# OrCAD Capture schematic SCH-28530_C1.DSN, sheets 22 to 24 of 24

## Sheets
22 24 PoE: size C
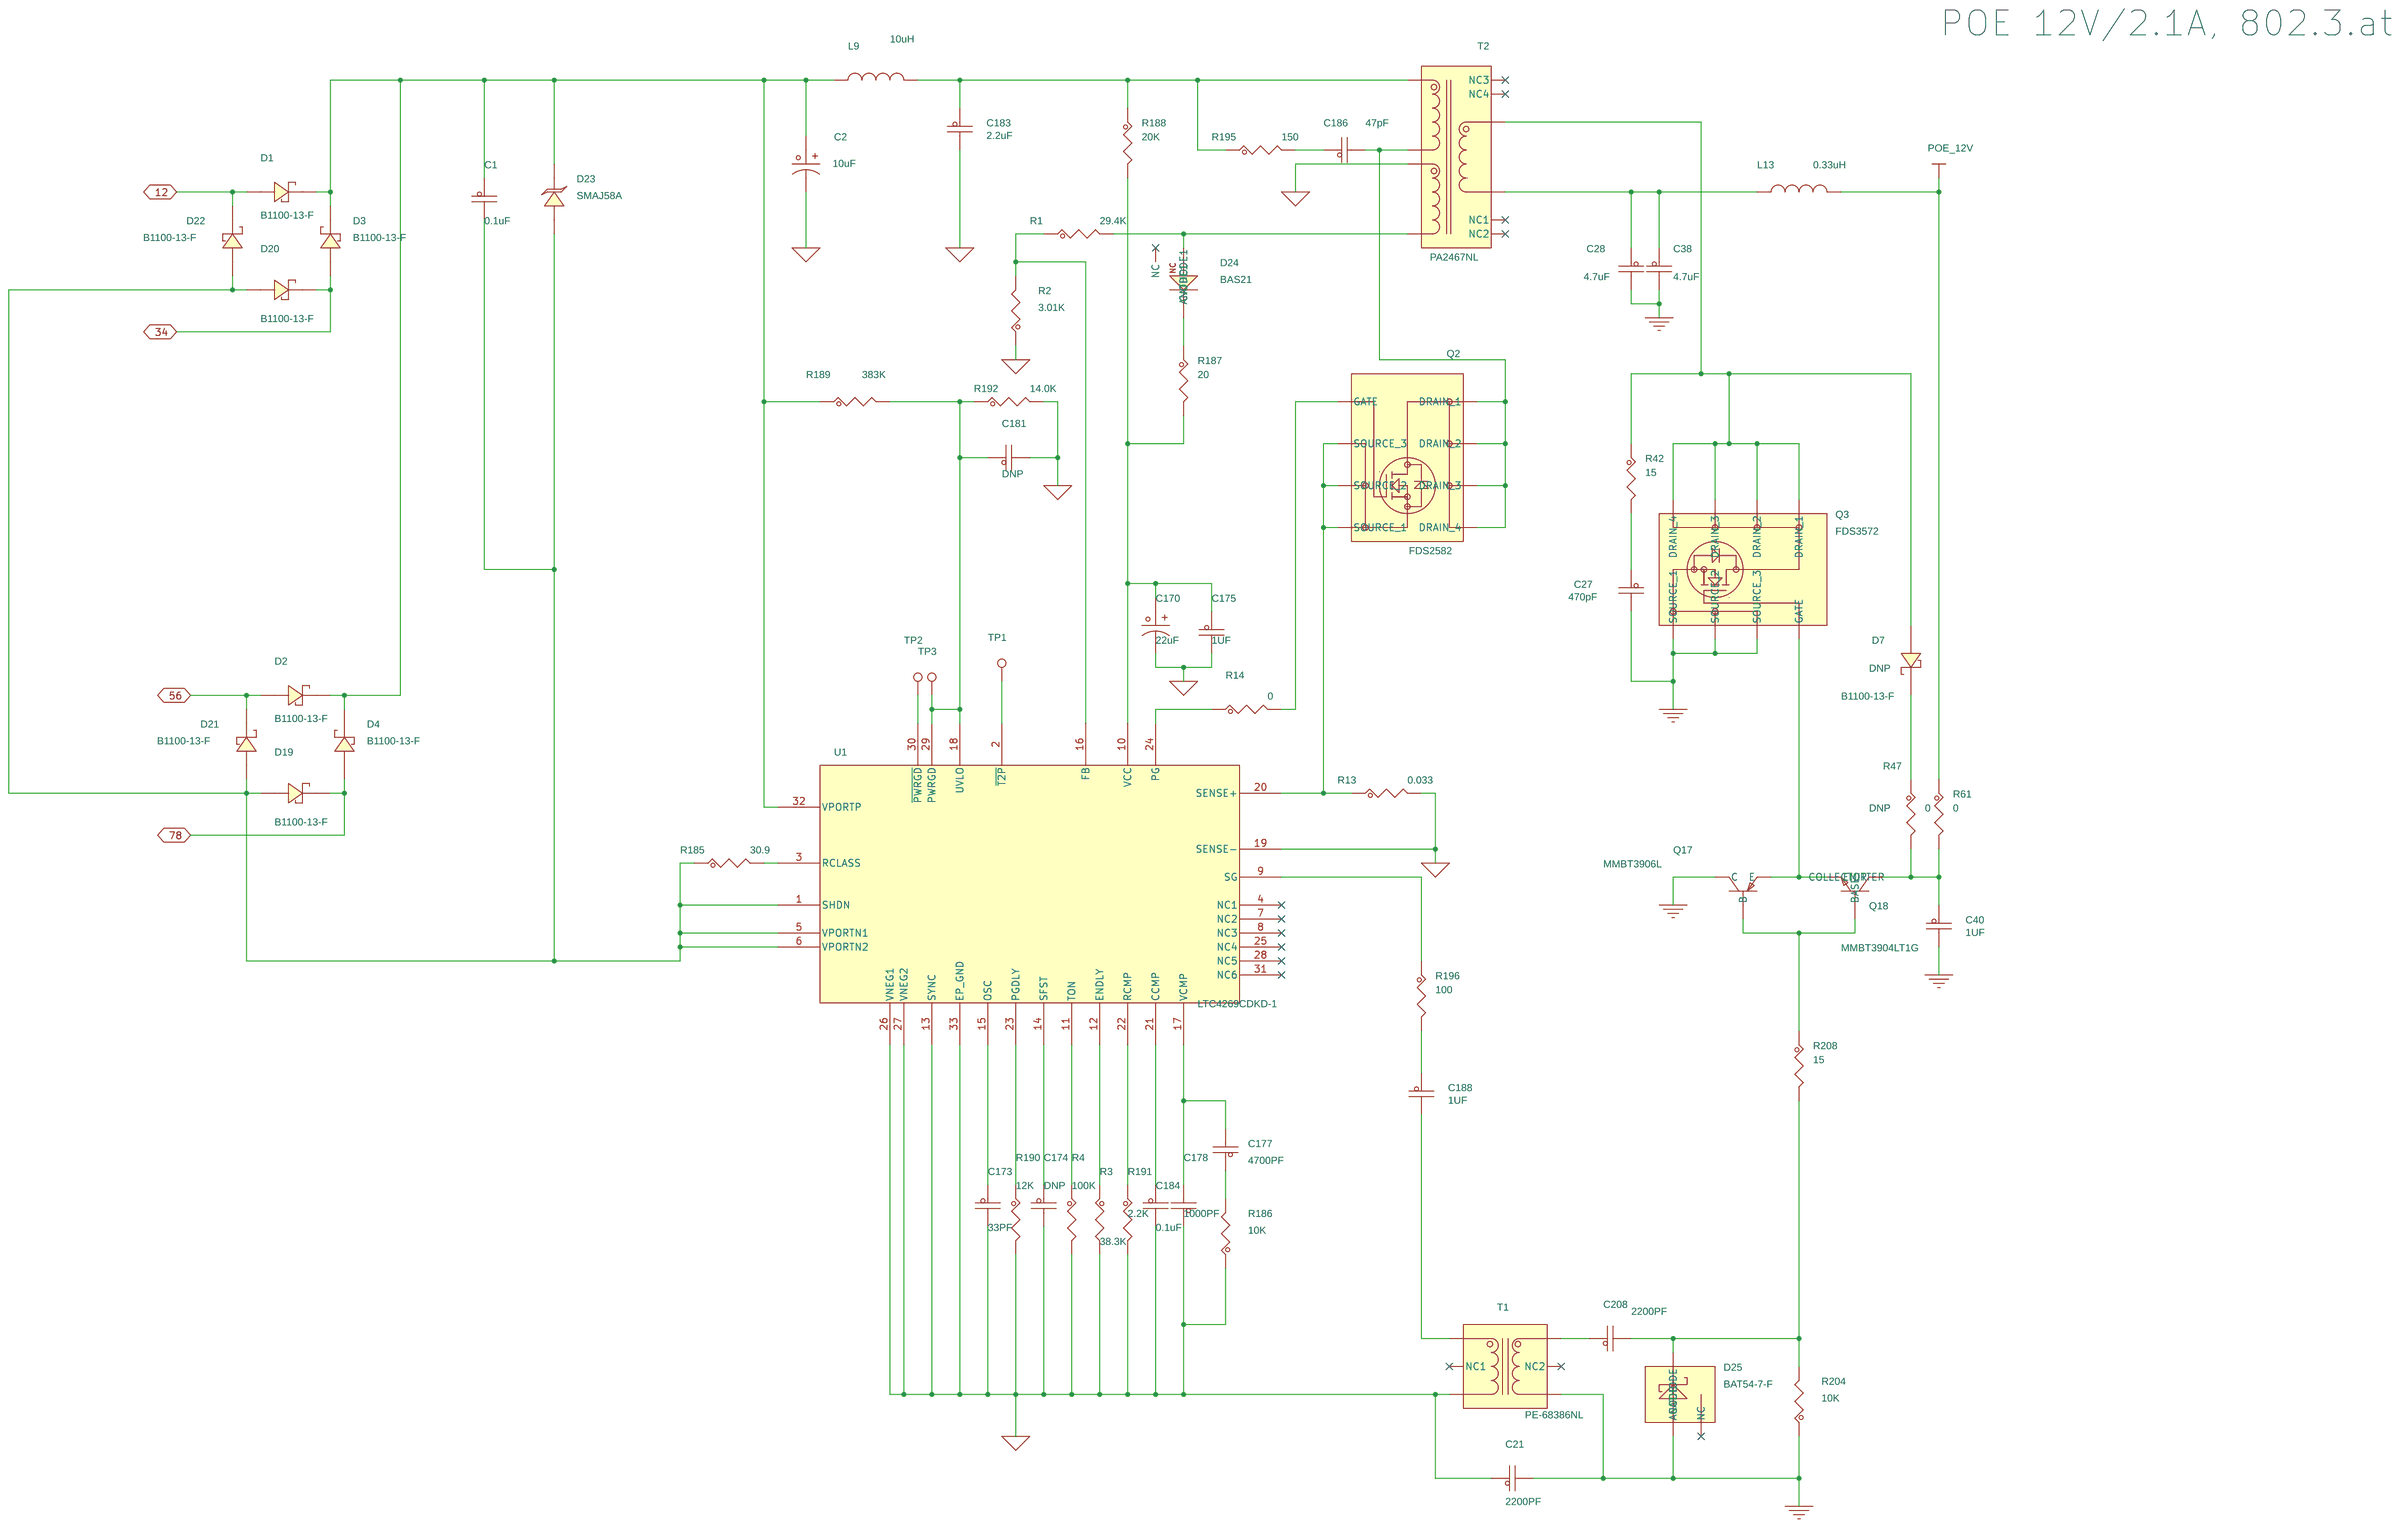
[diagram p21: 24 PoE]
23 21 V85/2V1/1V2/5V0: size C
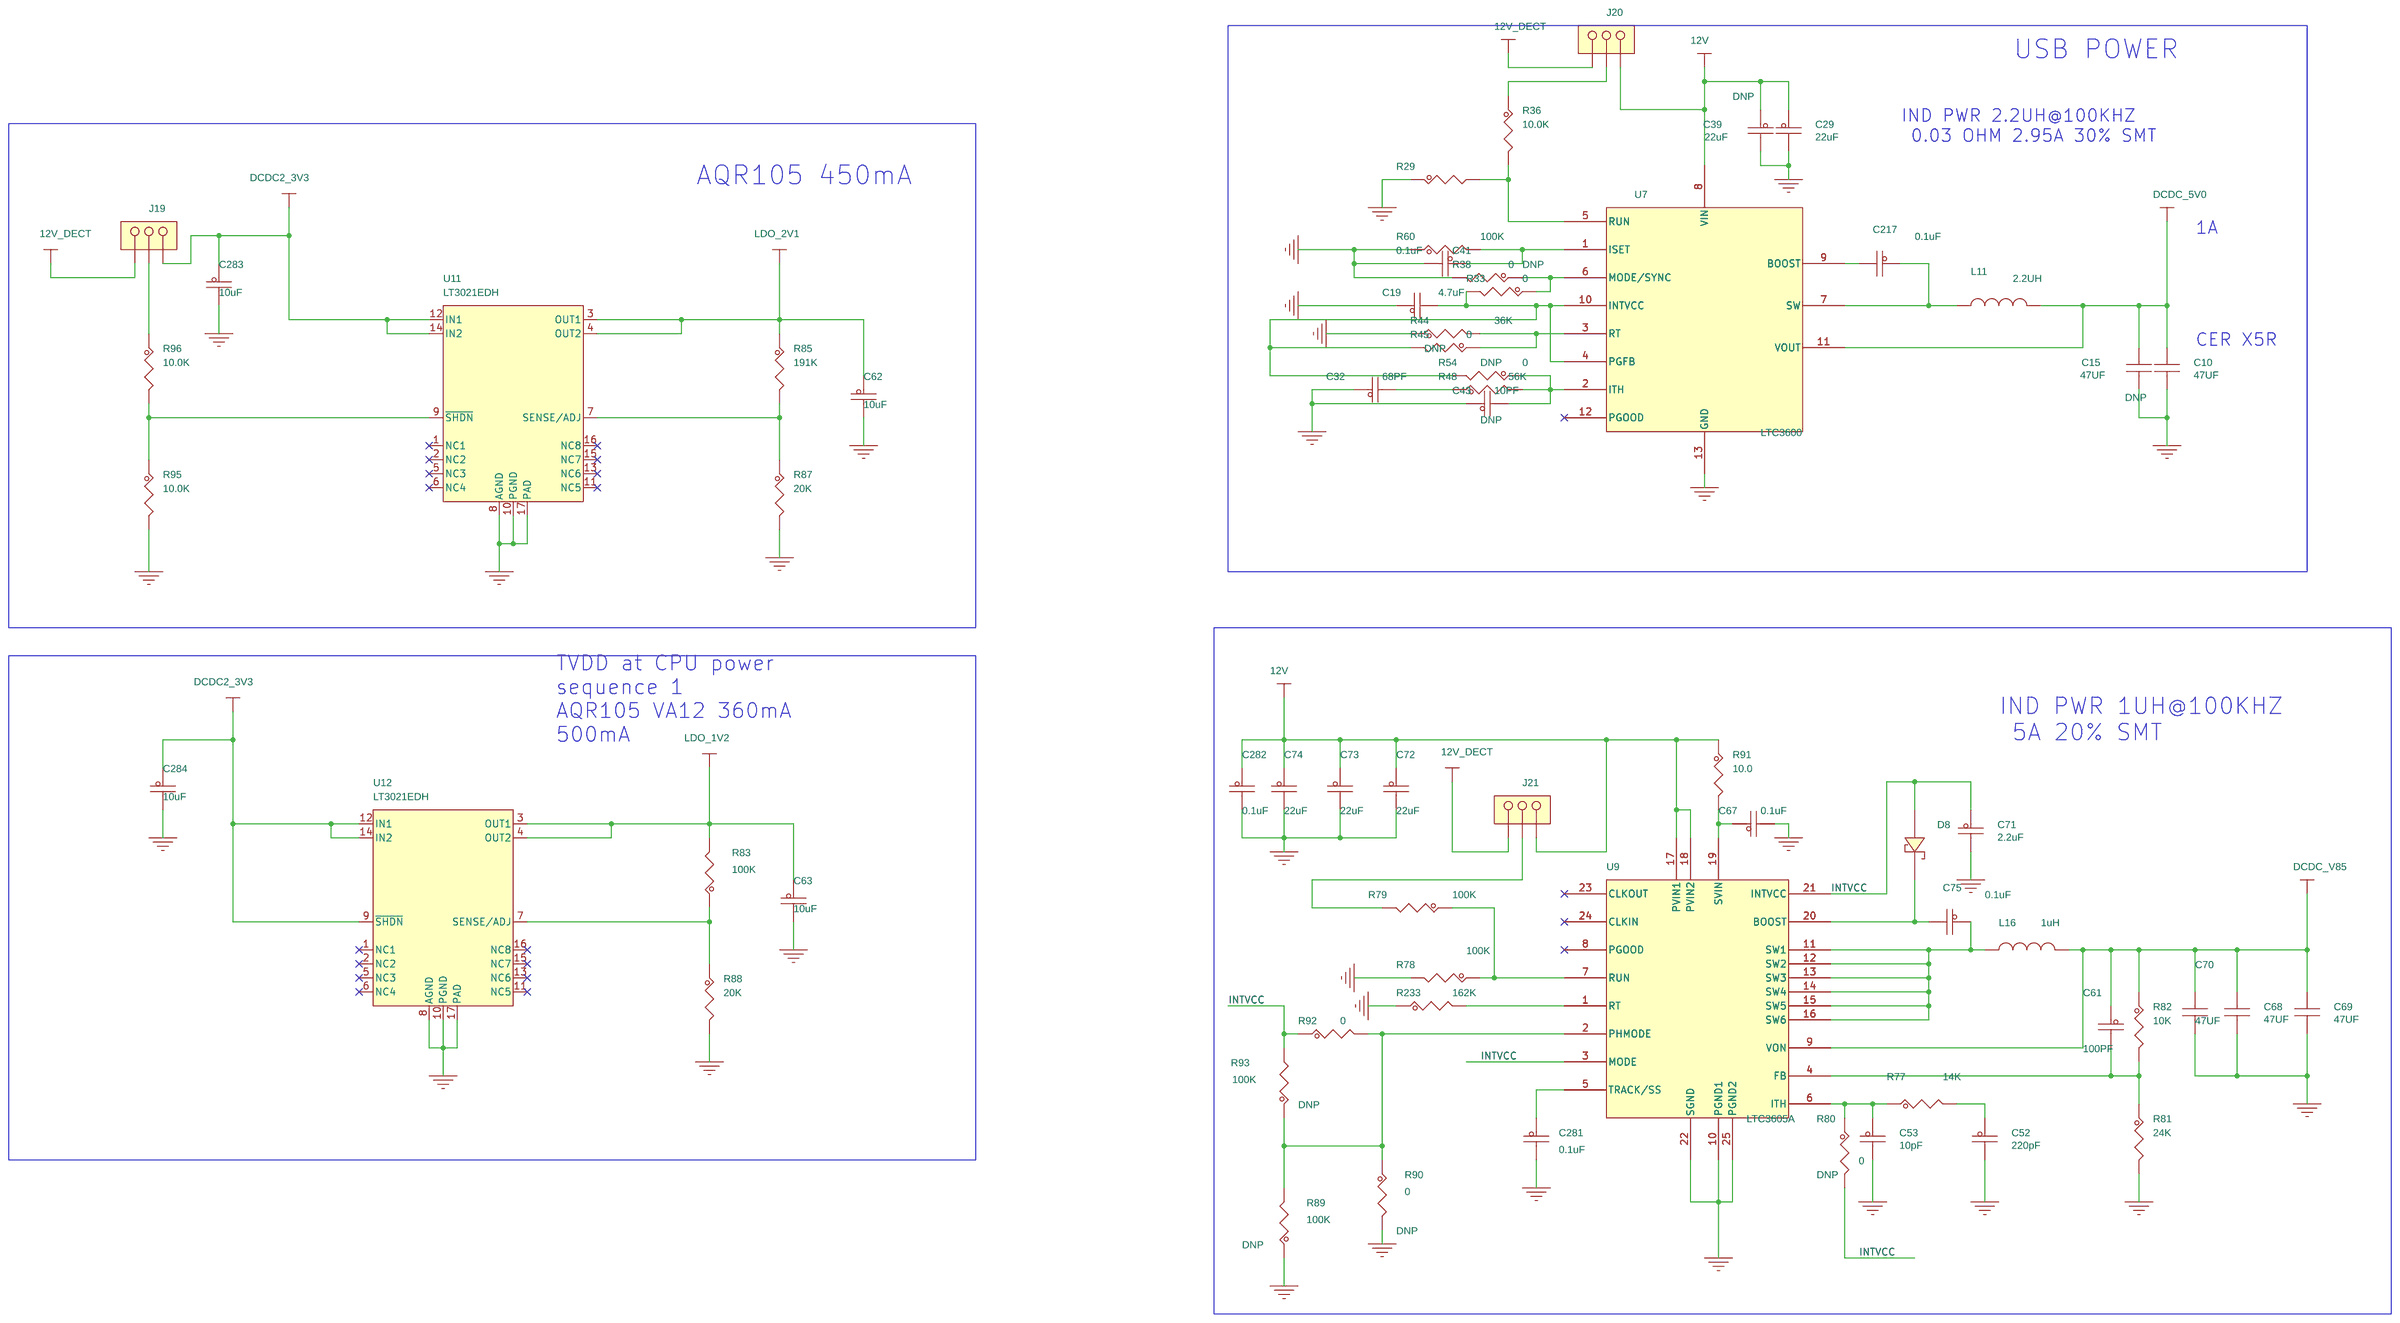
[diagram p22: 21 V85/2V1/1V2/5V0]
24 20 VR500(1V5/1V8/1V2/1V35/2V5): size C
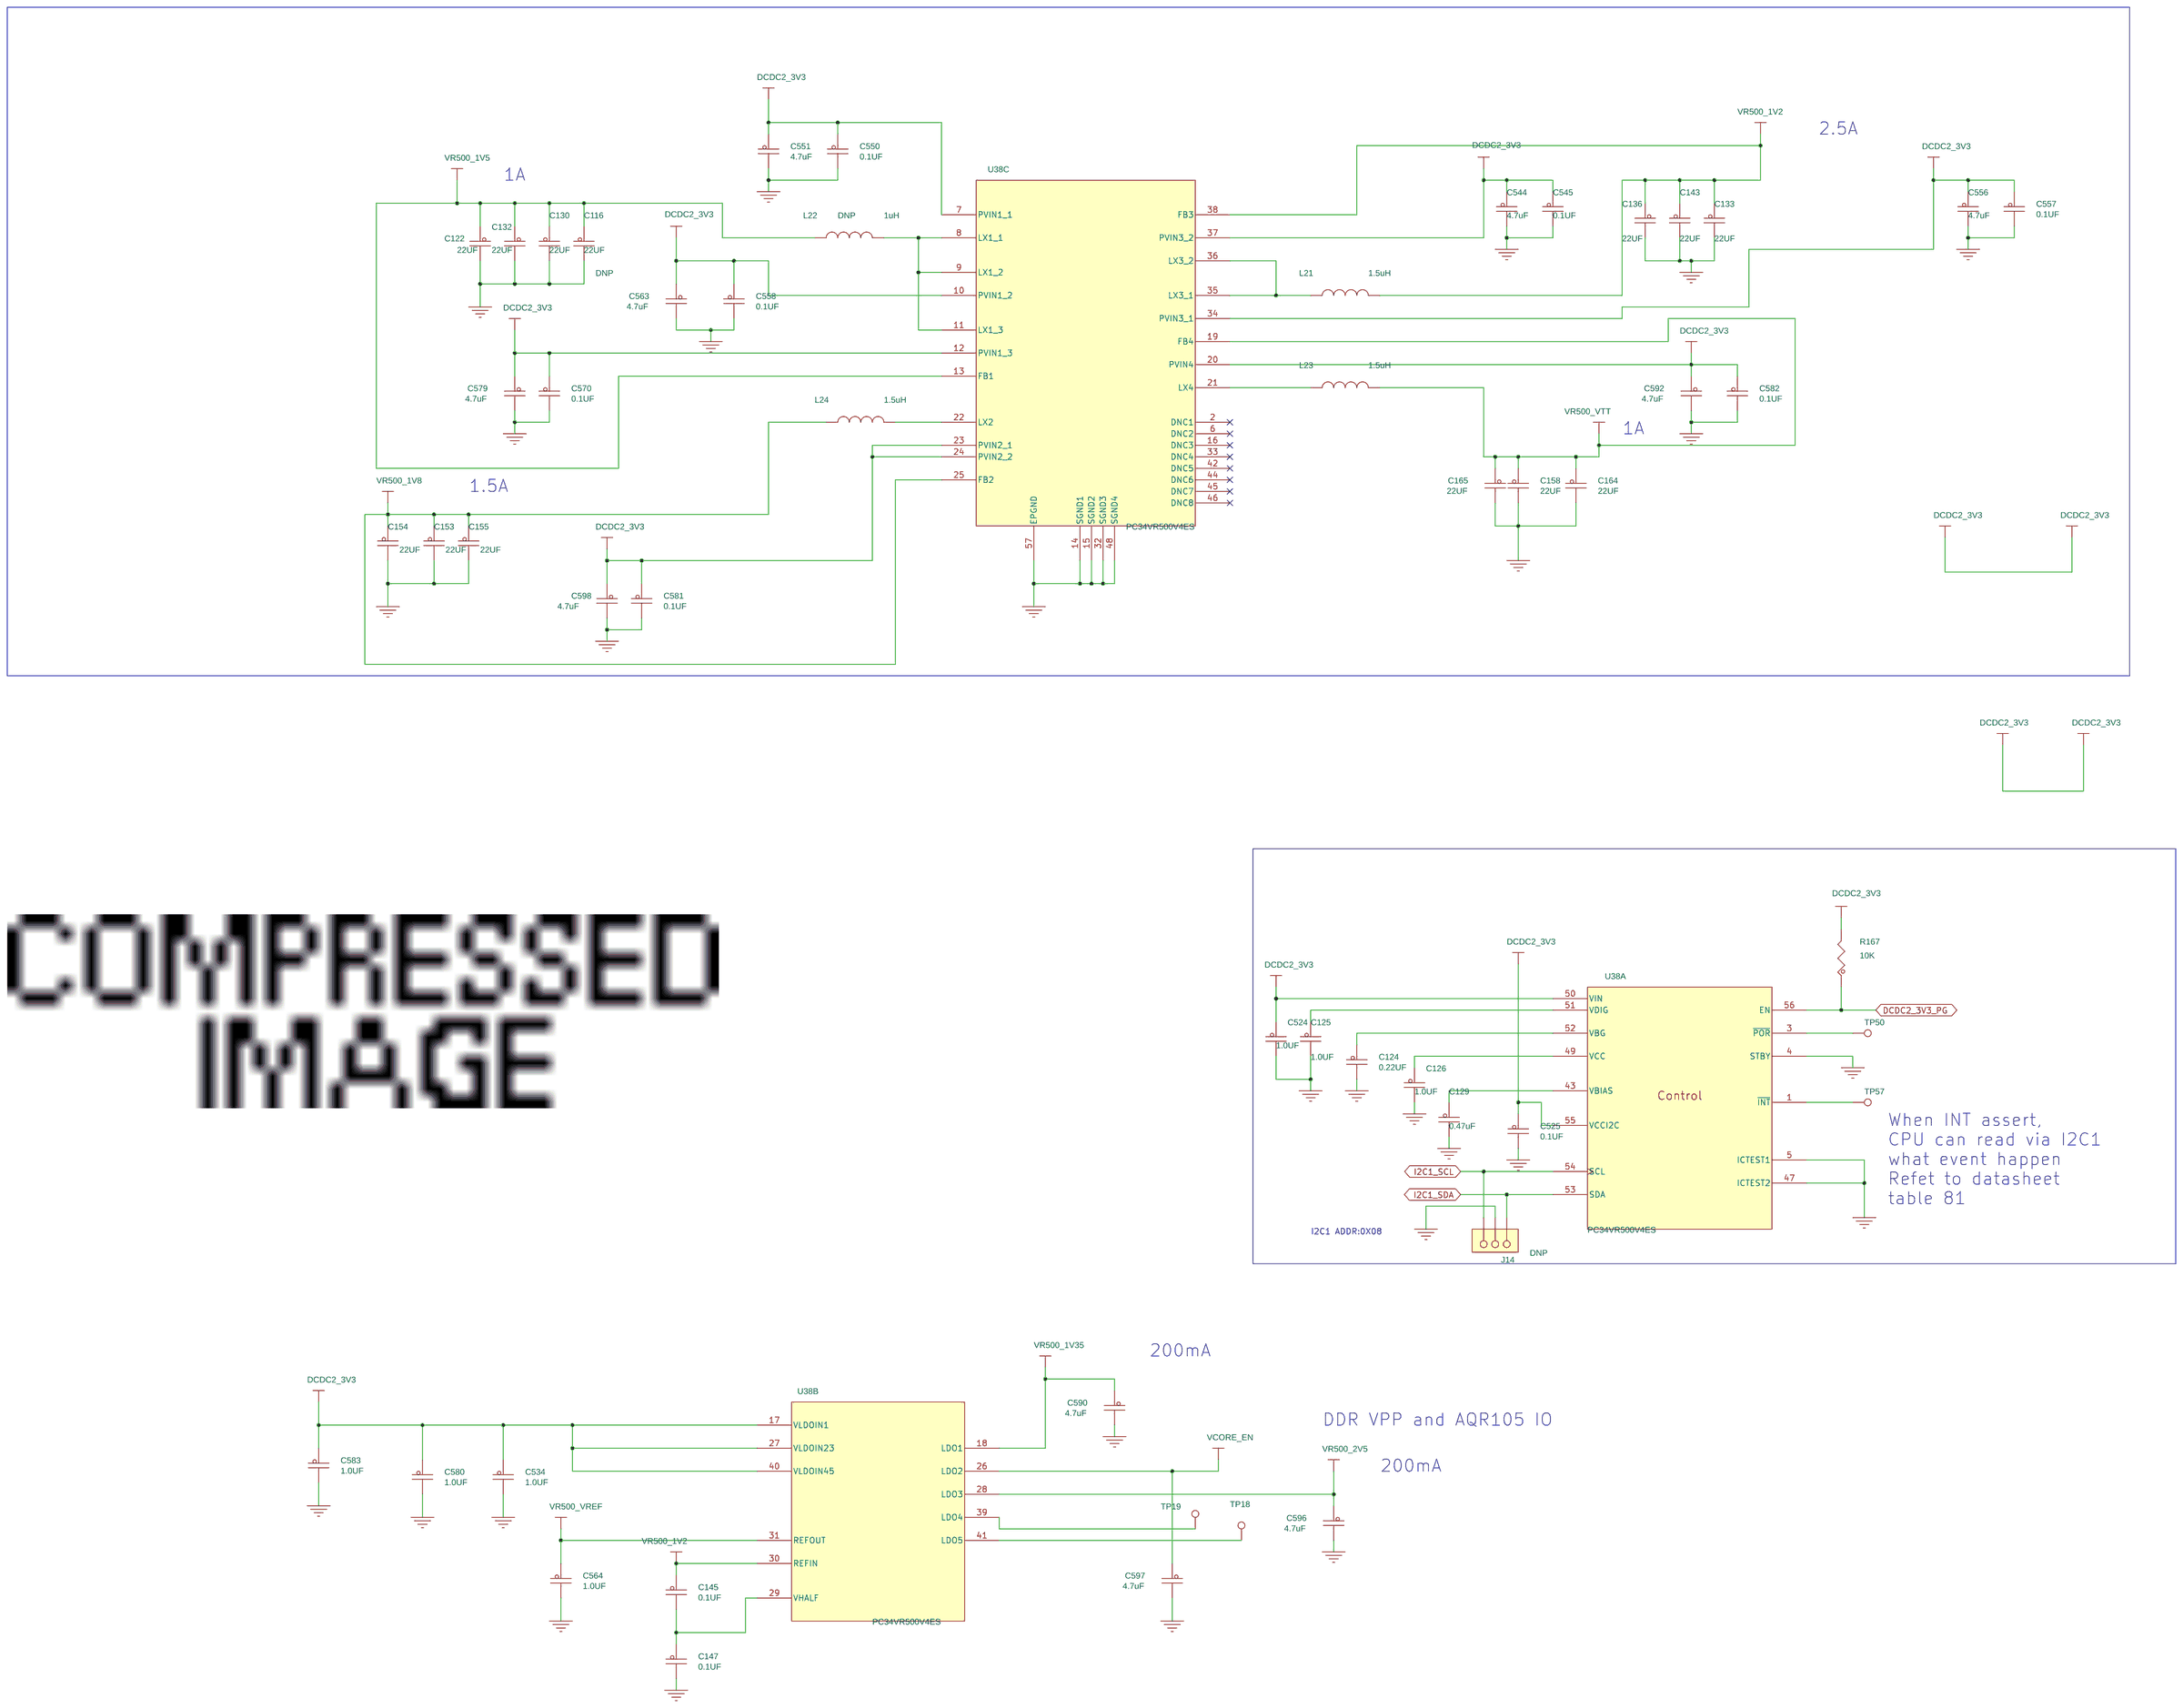
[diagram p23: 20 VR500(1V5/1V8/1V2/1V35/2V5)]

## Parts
sheet 20 VR500(1V5/1V8/1V2/1V35/2V5)
C116  22UF  [CC0805_OV]
C122  22UF  [CC0805_OV]
C124  0.22UF  [CC0402_25]
C125  1.0UF  [CC0402_25]
C126  1.0UF  [CC0402_25]
C129  0.47uF  [CC0402_25]
C130  22UF  [CC0805_OV]
C132  22UF  [CC0805_OV]
C133  22UF  [CC0805_OV]
C136  22UF  [CC0805_OV]
C143  22UF  [CC0805_OV]
C145  0.1UF  [CC0402_25]
C147  0.1UF  [CC0402_25]
C153  22UF  [CC0805_OV]
C154  22UF  [CC0805_OV]
C155  22UF  [CC0805_OV]
C158  22UF  [CC0805_OV]
C164  22UF  [CC0805_OV]
C165  22UF  [CC0805_OV]
C524  1.0UF  [CC0402_25]
C525  0.1UF  [CC0402_25]
C534  1.0UF  [CC0402_25]
C544  4.7uF  [CC0603_OV]
C545  0.1UF  [CC0402_25]
C550  0.1UF  [CC0402_25]
C551  4.7uF  [CC0603_OV]
C556  4.7uF  [CC0603_OV]
C557  0.1UF  [CC0402_25]
C558  0.1UF  [CC0402_25]
C563  4.7uF  [CC0603_OV]
C564  1.0UF  [CC0402_25]
C570  0.1UF  [CC0402_25]
C579  4.7uF  [CC0603_OV]
C580  1.0UF  [CC0402_25]
C581  0.1UF  [CC0402_25]
C582  0.1UF  [CC0402_25]
C583  1.0UF  [CC0402_25]
C590  4.7uF  [CC0603_OV]
C592  4.7uF  [CC0603_OV]
C596  4.7uF  [CC0603_OV]
C597  4.7uF  [CC0603_OV]
C598  4.7uF  [CC0603_OV]
J14  HDR TH 1X3  [HDR103]
L21  1.5uH  [ind2_4p3sq_xfl4020]
L22  1uH  [ind2_xal40]
L23  1.5uH  [ind2_4p3sq_xfl4020]
L24  1.5uH  [ind2_4p3sq_xfl4020]
R167  10K  [RC0603_OV]
TP18  35 MIL  [TESTPOINT_35MIL]
TP19  35 MIL  [TESTPOINT_35MIL]
TP50  35 MIL  [TESTPOINT_35MIL]
TP57  35 MIL  [TESTPOINT_35MIL]
U38  PC34VR500V4ES  [QFN56_0P5_8X8_EP4P1X4P4]  (sections A,B,C)
sheet 21 V85/2V1/1V2/5V0
C10  47UF  [CC1210]
C15  47UF  [CC1210]
C19  4.7uF  [CC0603_OV]
C29  22uF  [CC0805_OV]
C32  68PF  [CC0402_25]
C39  22uF  [CC0805_OV]
C41  0.1uF  [CC0402_25]
C43  10PF  [CC0603_OV]
C52  220pF  [CC0402_25]
C53  10pF  [CC0402_25]
C61  100PF  [CC0402_25]
C62  10uF  [CC0603_OV]
C63  10uF  [CC0603_OV]
C67  0.1uF  [CC0402_25]
C68  47UF  [CC1210]
C69  47UF  [CC1210]
C70  47UF  [CC1210]
C71  2.2uF  [CC0603_OV]
C72  22uF  [CC0805_OV]
C73  22uF  [CC0805_OV]
C74  22uF  [CC0805_OV]
C75  0.1uF  [CC0402_25]
C217  0.1uF  [CC0402_25]
C281  0.1uF  [CC0402_25]
C282  0.1uF  [CC0402_25]
C283  10uF  [CC0603_OV]
C284  10uF  [CC0603_OV]
D8  CMDSH-3 TR LEAD FREE  [SOD323]
J19  HDR_1X3  [hdr1x3_50mil]
J20  HDR_1X3  [hdr1x3_50mil]
J21  HDR_1X3  [hdr1x3_50mil]
L11  2.2UH  [IND2_4P3X4P3]
L16  1uH  [IND_DS3316]
R29  4.7K  [RC0402_25]
R33  0  [RC0402_25]
R36  10.0K  [RC0603_OV]
R38  0  [RC0402_25]
R44  36K  [RC0402_25]
R45  0  [RC0402_25]
R48  56K  [RC0402_25]
R54  0  [RC0402_25]
R60  100K  [RC0603_OV]
R77  14K  [RC0402_25]
R78  100K  [RC0603_OV]
R79  100K  [RC0603_OV]
R80  0  [RC0402_25]
R81  24K  [RC0603_OV]
R82  10K  [RC0603_OV]
R83  100K  [RC0603_OV]
R85  191K  [RC0402_25]
R87  20K  [RC0402_25]
R88  20K  [RC0402_25]
R89  100K  [RC0603_OV]
R90  0  [RC0402_25]
R91  10.0  [RC0402_25]
R92  0  [RC0402_25]
R93  100K  [RC0603_OV]
R95  10.0K  [RC0603_OV]
R96  10.0K  [RC0603_OV]
R233  162K  [RC0402_25]
U7  LTC3600  [dfn12_3x3_0p45]
U9  LTC3605A  [qfn24_4X4mm]
U11  LT3021EDH  [EDFN16_0P5_5X5_3P45X4P1]
U12  LT3021EDH  [EDFN16_0P5_5X5_3P45X4P1]
sheet 24 PoE
C1  0.1uF  [CC0603_OV]
C2  10uF  [case_f_8p5x8p5]
C21  2200PF  [cc1812_a]
C27  470pF  [CC0805_OV]
C28  4.7uF  [CC0603_OV]
C38  4.7uF  [CC0603_OV]
C40  1UF  [CC0603_OV]
C170  22uF  [cc3528-21]
C173  33PF  [CC0402_25]
C174  33PF  [CC0603_OV]
C175  1UF  [CC0603_OV]
C177  4700PF  [CC0603_OV]
C178  1000PF  [CC0603_OV]
C181  1UF  [CC0603_OV]
C183  2.2uF  [CC1210]
C184  0.1uF  [CC0603_OV]
C186  47pF  [CC0805_OV]
C188  1UF  [CC0603_OV]
C208  2200PF  [CC0603_OV]
D1  B1100-13-F  [sma2_4_4p6x2p9]
D2  B1100-13-F  [sma2_4_4p6x2p9]
D3  B1100-13-F  [sma2_4_4p6x2p9]
D4  B1100-13-F  [sma2_4_4p6x2p9]
D7  B1100-13-F  [sma2_4_4p6x2p9]
D19  B1100-13-F  [sma2_4_4p6x2p9]
D20  B1100-13-F  [sma2_4_4p6x2p9]
D21  B1100-13-F  [sma2_4_4p6x2p9]
D22  B1100-13-F  [sma2_4_4p6x2p9]
D23  SMAJ58A  [sma]
D24  BAS21  [sot23]
D25  BAT54-7-F  [sot23-40x40]
L9  10uH  [IND_DO1608]
L13  0.33uH  [ind_do1813]
Q2  FDS2582  [SO8_1P27_4X5]
Q3  FDS3572  [SO8]
Q17  MMBT3906L  [SOT23]
Q18  MMBT3904LT1G  [SOT23]
R1  29.4K  [RC0603_OV]
R2  3.01K  [RC0603_OV]
R3  38.3K  [RC0603_OV]
R4  100K  [RC0603_OV]
R13  0.033  [RC1206_OV]
R14  0  [RC0603_OV]
R42  15  [RC1206_OV]
R47  0  [RC0603_OV]
R61  0  [RC0603_OV]
R185  30.9  [RC0603_OV]
R186  10K  [RC0603_OV]
R187  20  [RC0603_OV]
R188  20K  [RC0402_25]
R189  383K  [RC0402_25]
R190  12K  [RC0603_OV]
R191  2.2K  [RC0603_OV]
R192  14.0K  [RC0603_OV]
R195  150  [RC1206_OV]
R196  100  [RC0603_OV]
R204  10K  [RC0603_OV]
R208  15  [RC0603_OV]
T1  PE-68386NL  [xfmr6_2p54_sm]
T2  PA2467NL  [xfmr10_2p5_13x14_sm]
TP1  35 MIL  [TESTPOINT_35MIL]
TP2  35 MIL  [TESTPOINT_35MIL]
TP3  35 MIL  [TESTPOINT_35MIL]
U1  LTC4269CDKD-1  [dfn32_0p4_4x7_ep]

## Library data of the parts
C116 = CAP_NP: CAP CER 22UF 10V 20% X5R 0805; AGILE_PN: 150-77793; ASSY_OPT: DNP; CAD_APPROVED: Yes; FPLIST: CC0805_OV,CC0805,0805_CC; HEIGHT: 1.45MM; MFG_NAME01: Taiyo Yuden; MFG_PN01: LMK212BJ226MG-T; ROHS: Yes; Tolerance: 20%; VOLTAGE: 10V
C122 C130 C132 C133 C136 C143 C153-C155 C158 C164 C165 = CAP_NP: CAP CER 22UF 10V 20% X5R 0805; AGILE_PN: 150-77793; CAD_APPROVED: Yes; FPLIST: CC0805_OV,CC0805,0805_CC; HEIGHT: 1.45MM; MFG_NAME01: Taiyo Yuden; MFG_PN01: LMK212BJ226MG-T; ROHS: Yes; Tolerance: 20%; VOLTAGE: 10V
C124 = CAP_NP: CAP CER 0.22UF 10V 10% X5R 0402; AGILE_PN: 150-77358; CAD_APPROVED: Yes; FPLIST: CC0402_25,CC0402_HD,0402_CC; HEIGHT: 0.55MM; MFG_NAME01: MURATA; MFG_PN01: GRM155R61A224KE19B; ROHS: Yes; Tolerance: 10%; VOLTAGE: 10V
C125 C126 C524 C534 C564 C580 C583 = CAP_NP: CAP CER 1.0UF 10V 10% X5R 0402; AGILE_PN: 150-75772; CAD_APPROVED: Yes; FPLIST: CC0402_25,CC0402_HD,0402_CC; HEIGHT: 0.6MM; MFG_NAME01: AVX; MFG_PN01: 0402ZD105KAT2A; ROHS: Yes; VOLTAGE: 10V
C129 = CAP_NP: CAP CER 0.47uF 10V 10% X5R 0402; AGILE_PN: 150-79395; CAD_APPROVED: Yes; FPLIST: CC0402_25,CC0402_HD,0402_CC; HEIGHT: 0.55MM; MFG_NAME01: Murata; MFG_PN01: GRM155R61A474KE15D; ROHS: Yes; Tolerance: 10%; VOLTAGE: 10V
C145 C147 C525 C545 C550 C557 C558 C570 C581 C582 = CAP_NP: CAP CER 0.1UF 10V 10% X5R 0402; AGILE_PN: 150-75634; CAD_APPROVED: Yes; FPLIST: CC0402_25,CC0402_HD,0402_CC; HEIGHT: 0.64MM; MFG_NAME01: KEMET; MFG_PN01: C0402C104K8PAC; ROHS: Yes; Tolerance: 10%; VOLTAGE: 10V
C544 C551 C556 C563 C579 C590 C592 C596-C598 = CAP_NP: CAP CER 4.7UF 10V 10% X5R 0603; AGILE_PN: 150-77975; CAD_APPROVED: Yes; FPLIST: CC0603_OV,CC0603,0603_CC; HEIGHT: 0.9MM; MFG_NAME01: TAIYO YUDEN; MFG_PN01: LMK107BJ475KA-T; ROHS: Yes; Tolerance: 10%; VOLTAGE: 10V
J14 = CONN_HDR_3X1: HDR 1X3 TH 100MIL SP 339H AU 100L; AGILE_PN: 210-75726; ASSY_OPT: DNP; CAD_APPROVED: Yes; HEIGHT: 8.65MM; MFG_NAME01: SAMTEC; MFG_PN01: TSW-103-07-G-S; ROHS: Yes
L21 L23 L24 = INDUCTOR: IND PWR 1.5uH@100KHz 4.1A 20% AEC-Q200 SMT; AGILE_PN: 180-78050; CAD_APPROVED: Yes; HEIGHT: 2.1 MM; MFG_NAME01: Coilcraft; MFG_PN01: XFL4020-152MEC; PART_TYPE: INDUCTOR\POWER; ROHS: Yes; Tolerance: 20%
L22 = INDUCTOR: IND PWR 1UH@100kHz 6A 20% SMT; AGILE_PN: 180-77903; ASSY_OPT: DNP; CAD_APPROVED: Yes; HEIGHT: 2.1MM; MFG_NAME01: Coilcraft; MFG_PN01: XAL4020-102MEC; PART_TYPE: INDUCTOR\POWER; ROHS: Yes; Tolerance: 20%
R167 = RES: RES MF 10K 1/10W 5% 0603; AGILE_PN: 470-75410; CAD_APPROVED: Yes; FPLIST: RC0603_OV,RC0603,0603_CC; HEIGHT: 0.55MM; MFG_NAME01: KOA SPEER; MFG_PN01: RK73B1JTTD103J; ROHS: Yes; Tolerance: 5%
TP1-TP3 TP18 TP19 TP50 TP57 = Test_pad: TEST PAD 35 MIL ROUND SMT; NO PART TO ORDER; AGILE_PN: 510-75219; CAD_APPROVED: Yes; HEIGHT: 0.1 MM; ROHS: Yes
U38 = MC34VR500V1ES_56P: IC POWER MANAGEMENT COMMUNICATION -0.3-4.8V QFN56; AGILE_PN: TMP-WF-23792; CAD_APPROVED: Yes; HEIGHT: 0.9 MM; MFG_NAME01: FREESCALE SEMICONDUCTOR; PRE_APN: 315-80527; ROHS: Yes
C10 C68-C70 = MOT_CAP: CAP CER 47UF 16V 10% X5R 1210; AGILE_PN: 150-75908; CAD_APPROVED: Yes; FPLIST: CC1210,1210_CC; HEIGHT: 2.7 mm; MFG_NAME01: MURATA; MFG_PN01: GRM32ER61C476KE15L; ROHS: Yes; Tolerance: 10%; VOLTAGE: 16V
C15 = MOT_CAP: CAP CER 47UF 16V 10% X5R 1210; AGILE_PN: 150-75908; ASSY_OPT: DNP; CAD_APPROVED: Yes; FPLIST: CC1210,1210_CC; HEIGHT: 2.7 mm; MFG_NAME01: MURATA; MFG_PN01: GRM32ER61C476KE15L; ROHS: Yes; Tolerance: 10%; VOLTAGE: 16V
C19 C28 C38 = CAP_NP: CAP CER 4.7uF 25V 10% X5R 0603; AGILE_PN: 150-79317; CAD_APPROVED: Yes; FPLIST: CC0603_OV,CC0603,0603_CC; HEIGHT: 0.95MM; MFG_NAME01: Murata; MFG_PN01: GRM188R61E475KE11D; ROHS: Yes; Tolerance: 10%; VOLTAGE: 25V
C29 C72-C74 = CAP_NP: CAP CER 22uF 25V 20% X5R 0805; AGILE_PN: 150-79304; FPLIST: CC0805_OV,CC0805,0805_CC; HEIGHT: 1.45MM; MFG_NAME01: MURATA; MFG_PN01: GRM21BR61E226ME44; ROHS: Yes; Tolerance: 20%; VOLTAGE: 25V
C32 = CAP_NP: CAP CER 68PF 50V 5% COG 0402; AGILE_PN: 150-76690; CAD_APPROVED: Yes; FPLIST: CC0402_25,CC0402_HD,0402_CC; HEIGHT: 0.55MM; MFG_NAME01: MURATA; MFG_PN01: GRM1555C1H680JA01D; ROHS: Yes; Tolerance: 5%; VOLTAGE: 50V
C39 = CAP_NP: CAP CER 22uF 25V 20% X5R 0805; AGILE_PN: 150-79304; ASSY_OPT: DNP; FPLIST: CC0805_OV,CC0805,0805_CC; HEIGHT: 1.45MM; MFG_NAME01: MURATA; MFG_PN01: GRM21BR61E226ME44; ROHS: Yes; Tolerance: 20%; VOLTAGE: 25V
C41 C67 C75 C217 C281 C282 = CAP_NP: CAP CER 0.1uF 16V 10% X7R AEC-Q200 0402; AGILE_PN: 150-79025; CAD_APPROVED: Yes; FPLIST: CC0402_25,CC0402_HD,0402_CC; HEIGHT: 0.55MM; MFG_NAME01: MURATA; MFG_PN01: GCM155R71C104KA55D; ROHS: Yes
C43 = CAP_NP: CAP CER 10PF 50V 5% C0G 0603; AGILE_PN: 150-30248; ASSY_OPT: DNP; CAD_APPROVED: Yes; FPLIST: CC0603_OV,CC0603,0603_CC; HEIGHT: 0.95MM; MFG_NAME01: MURATA; MFG_PN01: GCM1885C1H100JA16D; ROHS: Yes; Tolerance: 5%; VOLTAGE: 50V
C52 = CAP_NP: CAP CER 220PF 50V 10% X7R 0402; AGILE_PN: 150-75829; CAD_APPROVED: Yes; FPLIST: CC0402_25,CC0402_HD,0402_CC; HEIGHT: 0.55MM; MFG_NAME01: MURATA; MFG_PN01: GRM155R71H221KA01J; ROHS: Yes; Tolerance: 10%; VOLTAGE: 50V
C53 = CAP_NP: CAP CER 10pF 50V 2% C0G 0402; AGILE_PN: 150-78893; CAD_APPROVED: Yes; FPLIST: CC0402_25,CC0402_HD,0402_CC; HEIGHT: 0.55 MM; MFG_NAME01: MURATA; MFG_PN01: GJM1555C1H100GB01D; ROHS: Yes; Tolerance: 2%; VOLTAGE: 50V
C61 = CAP_NP: CAP CER 100pF 50V 1% C0G 0402; AGILE_PN: 150-79130; CAD_APPROVED: Yes; FPLIST: CC0402_25,CC0402_HD,0402_CC; HEIGHT: 0.56MM; MFG_NAME01: SAMSUNG; MFG_PN01: CL05C101FB5NNNC; ROHS: Yes; Tolerance: 1%; VOLTAGE: 50V
C62 C63 C283 C284 = CAP_NP: CAP CER 10uF 25V 20% X5R 0603; AGILE_PN: 150-79272; CAD_APPROVED: Yes; FPLIST: CC0603_OV,CC0603,0603_CC; HEIGHT: 1MM; MFG_NAME01: Murata; MFG_PN01: GRM188R61E106MA73D; ROHS: Yes; Tolerance: 20%; VOLTAGE: 25V
C71 = CAP_NP: CAP CER 2.2UF 16V 10% X5R 0603; AGILE_PN: 150-75417; CAD_APPROVED: YES; FPLIST: CC0603_OV,CC0603,0603_CC; HEIGHT: 0.9 MM; MFG_NAME01: MURATA; MFG_PN01: GRM188R61C225KE15D; ROHS: Yes; Tolerance: 10%; VOLTAGE: 16V
D8 = DIODE_SCHTKY: DIODE SCH PWR RECT 100MA 30V  SOD323; AGILE_PN: 480-30018; CAD_APPROVED: Yes; HEIGHT: 1.05 MM; MFG_NAME01: CENTRAL SEMICONDUCTOR; ROHS: Yes
J19-J21 = CONN_HDR_3X1: HDR 1X3 TH 50MIL SP 165H AU 91L; AGILE_PN: 210-80213; CAD_APPROVED: Yes; HEIGHT: 4.2MM; MFG_NAME01: SULLINS ELECTRONICS CORP; MFG_PN01: GRPB031VWVN-RC; ROHS: Yes
L11 = INDUCTOR: IND PWR 2.2UH@100KHZ 0.03 OHM 2.95A 30% SMT; AGILE_PN: 180-77799; CAD_APPROVED: Yes; HEIGHT: 3.0 MM; MFG_NAME01: Shenzhen Sunlord Electronics Co., Ltd; MFG_PN01: SWPA4030S2R2NT; PART_TYPE: INDUCTOR\POWER; ROHS: Yes; Tolerance: 30%
L16 = INDUCTOR: IND PWR 1UH@100KHZ 5A 20% SMT; AGILE_PN: 180-75275; CAD_APPROVED: Yes; HEIGHT: 5.08MM; MFG_NAME01: COILCRAFT; MFG_PN01: DS3316P-102ML; ROHS: Yes; Tolerance: 20%
R29 = RES: RES MF 4.7K 1/16W 5% 0402; AGILE_PN: 470-75626; CAD_APPROVED: Yes; FPLIST: RC0402_25,RC0402_HD,0402_CC; Function: UART; HEIGHT: 0.41mm; MFG_NAME01: KOA SPEER; MFG_PN01: RK73B1ETTP472J; ROHS: Yes; SIGNAL_MODEL: DEFAULT_RESISTOR_4700OHM_2_1; TOL: 5%; Tolerance: 5%
R33 R92 = RES: RES MF ZERO OHM 1/16W 5% 0402; AGILE_PN: 470-75394; CAD_APPROVED: Yes; FPLIST: RC0402_25,RC0402_HD,RC0402_X2,0402_CC; HEIGHT: 0.45 MM; MFG_NAME01: ROHM; MFG_PN01: MCR01MZPJ000; ROHS: Yes; SIGNAL_MODEL: RES_RC0402_25_DISCRETE_470-7539_0; Tolerance: 5%
R36 R95 R96 = RES: RES MF 10.0K 1/10W 1% 0603; AGILE_PN: 470-75422; CAD_APPROVED: Yes; FPLIST: RC0603_OV,RC0603,0603_CC; HEIGHT: 0.6MM; MFG_NAME01: KOA SPEER; MFG_PN01: RK73H1JTTD1002F; ROHS: Yes; Tolerance: 1%
R38 R45 R54 R80 R90 = RES: RES MF ZERO OHM 1/16W 5% 0402; AGILE_PN: 470-75394; ASSY_OPT: DNP; CAD_APPROVED: Yes; FPLIST: RC0402_25,RC0402_HD,RC0402_X2,0402_CC; HEIGHT: 0.45 MM; MFG_NAME01: ROHM; MFG_PN01: MCR01MZPJ000; ROHS: Yes; SIGNAL_MODEL: RES_RC0402_25_DISCRETE_470-7539_0; Tolerance: 5%
R44 = RES: RES MF 36K  1/16W 1% 0402; AGILE_PN: 470-31009; CAD_APPROVED: Yes; FPLIST: RC0402_25,RC0402_HD,0402_CC; HEIGHT: 0.40 MM; MFG_NAME01: KOA SPEER; MFG_PN01: RK73H1ETTP3602F; ROHS: Yes; Tolerance: 1%
R48 = RES: RES MF 56K  1/16W 1% 0402; AGILE_PN: 470-31032; CAD_APPROVED: Yes; FPLIST: RC0402_25,RC0402_HD,0402_CC; HEIGHT: 0.40 MM; MFG_NAME01: KOA SPEER; MFG_PN01: RK73H1ETTP5602F; ROHS: Yes; Tolerance: 1%
R4 R60 R78 R79 R83 = RES: RES MF 100K 1/10W 1% 0603; AGILE_PN: 470-75424; CAD_APPROVED: Yes; FPLIST: RC0603_OV,RC0603,0603_CC; HEIGHT: 0.6MM; MFG_NAME01: KOA SPEER; MFG_PN01: RK73H1JTTD1003F; ROHS: Yes; Tolerance: 1%
R77 = RES: RES MF 14K  1/16W 1% 0402; AGILE_PN: 470-30962; CAD_APPROVED: Yes; FPLIST: RC0402_25,RC0402_HD,0402_CC; HEIGHT: 0.40 MM; MFG_NAME01: KOA SPEER; MFG_PN01: RK73H1ETTP1402F; ROHS: Yes; Tolerance: 1%
R81 = RES: RES MF 24.0K 1/10W 1% 0603; AGILE_PN: 470-30236; CAD_APPROVED: Yes; FPLIST: RC0603_OV,RC0603,0603_CC; HEIGHT: 0.55 MM; MFG_NAME01: KOA SPEER; MFG_PN01: RK73H1JTTD2402F; ROHS: Yes; Tolerance: 1%
R82 = RES: RES MF 10K 1/8W 1% 0603; AGILE_PN: 470-80830; CAD_APPROVED: Yes; FPLIST: RC0603_OV,RC0603,0603_CC; HEIGHT: 0.5MM; MFG_NAME01: STACKPOLE ELECTRONICS; MFG_PN01: RNCP0603FTD10K0; ROHS: Yes; Tolerance: 1%
R85 = RES: RES MF 191K  1/16W 1% 0402; AGILE_PN: 470-31091; CAD_APPROVED: Yes; FPLIST: RC0402_25,RC0402_HD,0402_CC; HEIGHT: 0.40 MM; MFG_NAME01: KOA SPEER; MFG_PN01: RK73H1ETTP1913F; ROHS: Yes; Tolerance: 1%
R87 R88 R188 = RES: RES MF 20K 1/16W 1% 0402; AGILE_PN: 470-76103; CAD_APPROVED: Yes; FPLIST: RC0402_25,RC0402_HD,0402_CC; HEIGHT: 0.4MM; MFG_NAME01: WALSIN TECHNOLOGY CORP.; MFG_PN01: WR04X2002FTL; ROHS: Yes; Tolerance: 1%
R89 R93 = RES: RES MF 100K 1/10W 1% 0603; AGILE_PN: 470-75424; ASSY_OPT: DNP; CAD_APPROVED: Yes; FPLIST: RC0603_OV,RC0603,0603_CC; HEIGHT: 0.6MM; MFG_NAME01: KOA SPEER; MFG_PN01: RK73H1JTTD1003F; ROHS: Yes; Tolerance: 1%
R91 = RES: RES MF 10.0 OHM 1/16W 1% 0402; AGILE_PN: 470-76090; CAD_APPROVED: Yes; FPLIST: RC0402_25,RC0402_HD,0402_CC; HEIGHT: 0.4MM; MFG_NAME01: BOURNS; MFG_PN01: CR0402-FX-10R0GLF; ROHS: Yes; Tolerance: 1%
R233 = RES: RES MF 162K  1/16W 1% 0402; AGILE_PN: 470-31083; CAD_APPROVED: Yes; FPLIST: RC0402_25,RC0402_HD,0402_CC; HEIGHT: 0.40 MM; MFG_NAME01: KOA SPEER; MFG_PN01: RK73H1ETTP1623F; ROHS: Yes; Tolerance: 1%
U7 = LTC3600_12P_DFN_EP: IC VREG BUCK ADJ 1.5A 4-15V DFN12; AGILE_PN: 315-80445; CAD_APPROVED: Yes; HEIGHT: 0.8MM; MFG_NAME01: LINEAR TECHNOLOGY; MFG_PN01: LTC3600EDD#PBF; ROHS: Yes
U9 = LTC3605A_24P_QFN_EP: IC VREG BUCK SYNC ADJ 5A 4-20V QFN24; AGILE_PN: 315-80450; CAD_APPROVED: Yes; HEIGHT: 0.8MM; MFG_NAME01: LINEAR TECHNOLOGY; MFG_PN01: LTC3605AEUF#PBF; ROHS: Yes
U11 U12 = LT3021: IC REG ADJ 0.9V TO 10V 500MA; AGILE_PN: 312-75595; CAD_APPROVED: Yes; HEIGHT: 0.8MM; MFG_NAME01: LINEAR TECHNOLOGY; MFG_PN01: LT3021EDH#PBF; ROHS: Yes
C1 = CAP_NP: CAP CER 0.1uF 100V X7R 10% 0603; AGILE_PN: 150-79200; CAD_APPROVED: Yes; FPLIST: CC0603_OV,CC0603,0603_CC; HEIGHT: 0.9MM; MFG_NAME01: Murata; MFG_PN01: GRM188R72A104KA35D; ROHS: Yes; Tolerance: 10%; VOLTAGE: 100V
C2 = CAP_POL: CAP ALEL 10UF 100V 20% -- SMT; AGILE_PN: 150-79434; CAD_APPROVED: Yes; HEIGHT: 10.5MM; MFG_NAME01: LELON ELECTRONICS CORP; MFG_PN01: VE-100M2ATR-0810; ROHS: Yes; Tolerance: 20%; VOLTAGE: 100V
C21 = CAP_NP: CAP CER 2200PF 2KV 10% X7R 1812; AGILE_PN: 150-79429; CAD_APPROVED: Yes; HEIGHT: 2.03MM; MFG_NAME01: TDK; MFG_PN01: C4532X7R3D222K130KA; ROHS: Yes; Tolerance: 20%; VOLTAGE: 2KV
C27 = CAP_NP: CAP CER 470pF 100V 5% C0G 0805; AGILE_PN: 150-79127; CAD_APPROVED: Yes; FPLIST: CC0805_OV,CC0805,0805_CC; HEIGHT: 0.7 MM; MFG_NAME01: Murata; MFG_PN01: GRM2165C2A471JA01D; ROHS: Yes; Tolerance: 5%; VOLTAGE: 100V
C40 C175 C188 = CAP_NP: CAP CER 1uF 25V 10% X7R AEC-Q200 0603; AGILE_PN: 150-79081; CAD_APPROVED: Yes; FPLIST: CC0603_OV,CC0603,0603_CC; HEIGHT: 0.9MM; MFG_NAME01: TDK; MFG_PN01: CGA3E1X7R1E105K080AC; ROHS: Yes; Tolerance: 10%; VOLTAGE: 25V
C170 = CAP_POL: CAP TANT 22UF 16V 10% -- 3528-21; AGILE_PN: 150-78521; CAD_APPROVED: Yes; HEIGHT: 2.1MM; MFG_NAME01: AVX; MFG_PN01: TAJB226K016RNJ; ROHS: Yes; Tolerance: 10%; VOLTAGE: 16V
C173 = CAP_NP: CAP CER 33PF 50V 1% C0G 0402; AGILE_PN: 150-30259; CAD_APPROVED: Yes; FPLIST: CC0402_25,CC0402_HD,0402_CC; HEIGHT: 0.74MM; MFG_NAME01: AVX; MFG_PN01: 04025A330FAT2A; ROHS: Yes; Tolerance: 1%; VOLTAGE: 50V
C174 = CAP_NP: CAP CER 33PF 50V 5% C0G 0603; AGILE_PN: 150-75138; ASSY_OPT: DNP; CAD_APPROVED: Yes; FPLIST: CC0603_OV,CC0603,0603_CC; HEIGHT: 0.90MM; MFG_NAME01: VENKEL COMPANY; MFG_PN01: C0603C0G500-330JNE; ROHS: Yes; Tolerance: 5%; VOLTAGE: 50V
C177 = CAP_NP: CAP CER 4700PF 50V 10% X7R 0603; AGILE_PN: 150-30078; CAD_APPROVED: Yes; FPLIST: CC0603_OV,CC0603,0603_CC; HEIGHT: 0.90MM; MFG_NAME01: YAGEO AMERICA; MFG_PN01: CC0603KRX7R9BB472; ROHS: Yes; Tolerance: 10%; VOLTAGE: 50V
C178 = CAP_NP: CAP CER 1000PF 50V 10% X7R 0603; AGILE_PN: 150-75140; CAD_APPROVED: YES; FPLIST: CC0603_OV,CC0603,0603_CC; HEIGHT: 0.9MM; MFG_NAME01: VENKEL COMPANY; MFG_PN01: C0603X7R500-102KNE; ROHS: Yes; Tolerance: 10%; VOLTAGE: 50V
C181 = CAP_NP: CAP CER 1uF 25V 10% X7R AEC-Q200 0603; AGILE_PN: 150-79081; ASSY_OPT: DNP; CAD_APPROVED: Yes; FPLIST: CC0603_OV,CC0603,0603_CC; HEIGHT: 0.9MM; MFG_NAME01: TDK; MFG_PN01: CGA3E1X7R1E105K080AC; ROHS: Yes; Tolerance: 10%; VOLTAGE: 25V
C183 = CAP_NP: CAP CER 2.2UF 100V 10% X7R 1210; AGILE_PN: 150-77671; CAD_APPROVED: Yes; FPLIST: CC1210,1210_CC; HEIGHT: 2.7MM; MFG_NAME01: Murata; MFG_PN01: GRM32ER72A225KA35L; ROHS: Yes; Tolerance: 10%; VOLTAGE: 100V
C184 = CAP_NP: CAP CER 0.1UF 50V 5% X7R 0603; AGILE_PN: 150-79008; CAD_APPROVED: Yes; FPLIST: CC0603_OV,CC0603,0603_CC; HEIGHT: 0.9 MM; MFG_NAME01: AVX; MFG_PN01: 06035C104JAT2A; ROHS: Yes; Tolerance: 5%; VOLTAGE: 50V
C186 = CAP_NP: CAP CER 47pF 250V 1% C0G 0805; AGILE_PN: 150-79301; CAD_APPROVED: Yes; FPLIST: CC0805_OV,CC0805,0805_CC; HEIGHT: 1.44MM; MFG_NAME01: AMERICAN TECHNICAL CERAMICS CORP; MFG_PN01: 600F470FT250XT; ROHS: Yes; Tolerance: 1%; VOLTAGE: 250V
C208 = CAP_NP: CAP CER 2200PF 50V 10% X7R 0603; AGILE_PN: 150-75275; CAD_APPROVED: Yes; FPLIST: CC0603_OV,CC0603,0603_CC; HEIGHT: 0.9652MM; MFG_NAME01: AVX; MFG_PN01: 06035C222KAT2A; ROHS: Yes; Tolerance: 10%; VOLTAGE: 50V
D1-D4 D19-D22 = DIODE_SCHTKY: DIODE SCH RECT 1A 100V SMA; AGILE_PN: 480-78012; CAD_APPROVED: Yes; HEIGHT: 2.3MM; MFG_NAME01: DIODES INC; ROHS: Yes
D7 = DIODE_SCHTKY: DIODE SCH RECT 1A 100V SMA; AGILE_PN: 480-78012; ASSY_OPT: DNP; CAD_APPROVED: Yes; HEIGHT: 2.3MM; MFG_NAME01: DIODES INC; ROHS: Yes
D23 = DIODE_TVS: DIODE TVS -- 58V 400W SMA; AGILE_PN: 480-77298; CAD_APPROVED: Yes; HEIGHT: 2.62MM; MFG_NAME01: DIODES INC; MFG_PN01: SMAJ58A-13-F; ROHS: Yes
D24 = DIODE_SOT23: DIODE SW 200MA 200V SOT23; AGILE_PN: 480-77994; CAD_APPROVED: Yes; HEIGHT: 1.1MM; MFG_NAME01: PHILIPS SEMICONDUCTOR; ROHS: Yes
D25 = DIODE_SCH_BAT54: DIODE SCH 200mA 30V SOT23; AGILE_PN: 480-78267; CAD_APPROVED: Yes; HEIGHT: 1.2MM; MFG_NAME01: DIODES INC; ROHS: Yes
L9 = INDUCTOR: IND PWR 10UH@100KHZ 1.1A 20% SMT; AGILE_PN: 180-75002; CAD_APPROVED: Yes; HEIGHT: 2.92mm; MFG_NAME01: COILCRAFT; MFG_PN01: DO1608C-103ML_; PART_TYPE: POWER; ROHS: Yes; Tolerance: 20%
L13 = INDUCTOR: IND PWR 0.33uH@100KHZ 10A 20% SMT; AGILE_PN: 180-78297; CAD_APPROVED: Yes; HEIGHT: 5MM; MFG_NAME01: COILCRAFT; MFG_PN01: DO1813H-331MLB; PART_TYPE: INDUCTOR\POWER; ROHS: Yes; Tolerance: 20%
Q2 = MOSFET_N_8P: TRAN NMOS PWR 4.1A 150V SOIC8; AGILE_PN: 480-78826; CAD_APPROVED: Yes; HEIGHT: 1.75MM; MFG_NAME01: Fairchild; ROHS: Yes
Q3 = MOSFET_N_8P: TRAN NMOS PWR 8.9A 80V SO8; AGILE_PN: 480-78828; CAD_APPROVED: Yes; HEIGHT: 1.75 MM; MFG_NAME01: FAIRCHILD; ROHS: Yes
Q17 = PNP: TRAN PNP GEN 0.2A 40V SOT23; AGILE_PN: 480-75192; CAD_APPROVED: Yes; HEIGHT: 1.3MM; MFG_NAME01: ON SEMICONDUCTOR; MFG_PN01: MMBT3906LT1G; ROHS: Yes
Q18 = NPN: TRAN NPN GEN 200MA 40V SOT-23; AGILE_PN: 480-75173; CAD_APPROVED: Yes; HEIGHT: 1.12 MM; MFG_NAME01: ON SEMICONDUCTOR; ROHS: Yes
R1 = RES: RES MF 29.4K 1/10W 1% 0603; AGILE_PN: 470-75533; CAD_APPROVED: Yes; FPLIST: RC0603_OV,RC0603,0603_CC; HEIGHT: 0.55 MM; MFG_NAME01: KOA SPEER; MFG_PN01: RK73H1JTTD2942F; ROHS: Yes; Tolerance: 1%
R2 = RES: RES MF 3.01K 1/10W 1% 0603; AGILE_PN: 470-30483; CAD_APPROVED: Yes; FPLIST: RC0603_OV,RC0603,0603_CC; HEIGHT: 0.6MM; MFG_NAME01: KOA SPEER; MFG_PN01: RK73H1JTTD3011F; ROHS: Yes; Tolerance: 1%
R3 = RES: RES MF 38.3K 1/10W 1% 0603; AGILE_PN: 470-78071; CAD_APPROVED: Yes; FPLIST: RC0603_OV,RC0603,0603_CC; HEIGHT: 0.55MM; MFG_NAME01: KOA SPEER; MFG_PN01: RK73H1JTTD3832F; ROHS: Yes; Tolerance: 1%
R13 = RES: RES MF 0.033 OHM 1/2W 1% AEC-Q200 1206; AGILE_PN: 470-80928; CAD_APPROVED: Yes; FPLIST: RC1206_OV,RC1206,1206_CC; HEIGHT: 0.8MM; MFG_NAME01: TT ELECTRONICS PLC; MFG_PN01: LRC-LR1206LF-01-R033F; ROHS: Yes; Tolerance: 1%
R14 R61 = RES: RES MF ZERO OHM 1/10W -- AEC-Q200 0603; AGILE_PN: 470-75407; CAD_APPROVED: Yes; FPLIST: RC0603_OV,RC0603,R603-X2,0603_CC; HEIGHT: 0.6MM; MFG_NAME01: KOA SPEER; MFG_PN01: RK73Z1JTTD; ROHS: Yes; Tolerance: 1%
R42 = RES: RES MF 15.0 OHM 1/4W 1% 1206; AGILE_PN: 470-30123; CAD_APPROVED: Yes; FPLIST: RC1206_OV,RC1206,1206_CC; HEIGHT: 0.6MM; MFG_NAME01: VISHAY INTERTECHNOLOGY; MFG_PN01: CRCW120615R0FKEA; ROHS: Yes; Tolerance: 1%
R47 = RES: RES MF ZERO OHM 1/10W -- AEC-Q200 0603; AGILE_PN: 470-75407; ASSY_OPT: DNP; CAD_APPROVED: Yes; FPLIST: RC0603_OV,RC0603,R603-X2,0603_CC; HEIGHT: 0.6MM; MFG_NAME01: KOA SPEER; MFG_PN01: RK73Z1JTTD; ROHS: Yes; Tolerance: 1%
R185 = RES: RES MF 30.9 OHM  1/10W 1% 0603; AGILE_PN: 470-77869; CAD_APPROVED: Yes; FPLIST: RC0603_OV,RC0603,0603_CC; HEIGHT: 0.55MM; MFG_NAME01: KOA SPEER; MFG_PN01: RK73H1JTTD30R9F; ROHS: Yes; Tolerance: 1%
R186 R204 = RES: RES MF 10K 1/10W 1% AEC-Q200 0603; AGILE_PN: 470-80526; CAD_APPROVED: Yes; FPLIST: RC0603_OV,RC0603,0603_CC; HEIGHT: 0.55 MM; MFG_NAME01: VISHAY INTERTECHNOLOGY; MFG_PN01: CRCW060310K0FKEA; ROHS: Yes; Tolerance: 1%
R187 = RES: RES MF 20.0OHM 1/10W 1% 0603; AGILE_PN: 470-75405; CAD_APPROVED: Yes; FPLIST: RC0603_OV,RC0603,0603_CC; HEIGHT: 0.55 MM; MFG_NAME01: KOA SPEER; MFG_PN01: RK73H1JTTD20R0F; ROHS: Yes; Tolerance: 1%
R189 = RES: RES MF 383K  1/16W 1% 0402; AGILE_PN: 470-31125; CAD_APPROVED: Yes; FPLIST: RC0402_25,RC0402_HD,0402_CC; HEIGHT: 0.4 MM; MFG_NAME01: KOA SPEER; MFG_PN01: RK73H1ETTP3833F; ROHS: Yes; Tolerance: 1%
R190 = RES: RES MF 12K 1/10W 5% 0603; AGILE_PN: 470-75446; CAD_APPROVED: Yes; FPLIST: RC0603_OV,RC0603,0603_CC; HEIGHT: 0.55MM; MFG_NAME01: BOURNS; MFG_PN01: CR0603-JW-123ELF; ROHS: Yes; Tolerance: 5%
R191 = RES: RES MF 2.2K 1/10W 5% 0603; AGILE_PN: 470-75399; CAD_APPROVED: Yes; FPLIST: RC0603_OV,RC0603,0603_CC; HEIGHT: 0.55MM; MFG_NAME01: VENKEL COMPANY; MFG_PN01: CR0603-10W-222JT; ROHS: Yes; Tolerance: 5%
R192 = RES: RES MF 14.0K 1/10W 1% 0603; AGILE_PN: 470-78047; CAD_APPROVED: Yes; FPLIST: RC0603_OV,RC0603,0603_CC; HEIGHT: 0.55MM; MFG_NAME01: KOA SPEER; MFG_PN01: RK73H1JTTD1402F; ROHS: Yes; Tolerance: 1%
R195 = RES: RES MF 150 OHM 1/4W 1% 1206; AGILE_PN: 470-30054; CAD_APPROVED: Yes; FPLIST: RC1206_OV,RC1206,1206_CC; HEIGHT: 0.6MM; MFG_NAME01: VISHAY INTERTECHNOLOGY; MFG_PN01: CRCW1206150RFKEA; ROHS: Yes; Tolerance: 1%
R196 = RES: RES MF 100 OHM 1/10W 1% 0603; AGILE_PN: 470-80885; CAD_APPROVED: Yes; FPLIST: RC0603_OV,RC0603,0603_CC; HEIGHT: 0.6mm; MFG_NAME01: YAGEO AMERICA; MFG_PN01: RC0603FR-07100RL; ROHS: Yes
R208 = RES: RES MF 15 OHM 1/10W 5% 0603; AGILE_PN: 470-75396; CAD_APPROVED: Yes; FPLIST: RC0603_OV,RC0603,0603_CC; HEIGHT: 0.55MM; MFG_NAME01: KOA SPEER; MFG_PN01: RK73B1JTTD150J; ROHS: Yes; Tolerance: 5%
T1 = PE-68386_6P: XFMR 1:1 785uH 1500VDC SMT; AGILE_PN: 560-75676; CAD_APPROVED: Yes; HEIGHT: 2.5MM; MFG_NAME01: PULSE; PART_TYPE: TRANSFORMERS; ROHS: Yes
T2 = PA2467_10P: XFMR FLYBACK 12V 2.1A 37V-57V SMD; AGILE_PN: TMP-WF-23372; CAD_APPROVED: Yes; HEIGHT: 12.32MM; MFG_NAME01: PULSE ENGINEERING; PART_TYPE: TRANSFORMERS; PRE_APN: 560-75677; ROHS: Yes
U1 = LTC4269-1_32P_EP: IC PD CTRL W/ REG 25.5W 60V DFN32; AGILE_PN: 315-80444; CAD_APPROVED: Yes; HEIGHT: 0.8MM; MFG_NAME01: LINEAR TECHNOLOGY; MFG_PN01: LTC4269CDKD-1#PBF; ROHS: Yes

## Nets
12V: C29.1 C39.1 C72.1 C73.1 C74.1 C282.1 J20.3 J21.3 R91.1 U7.8(VIN) U9.17(PVIN1) U9.18(PVIN2) ; also on sheet 18 20 21
12V_DECT: J19.1 J20.1 J21.1 ; also on sheet 18 20 21
AVDD_CGA1: C153.1 C154.1 C155.1 L24.1 U38.25(FB2) ; also on sheet 6 7 8 9 11 12 13 20 21
AVDD_SD1_PLL1: C590.1 U38.18(LDO1) ; also on sheet 9 11 12
GND: C10.2 C15.2 C19.1 C21.2 C27.2 C28.2 C29.2 C32.1 C38.2 C39.2 C40.2 C41.2 C43.1 C52.2 C53.2 C62.2 C63.2 C67.2 C68.2 C69.2 C70.2 C71.2 C72.2 C73.2 C74.2 C116.2 C122.2 C124.2 C125.2 C126.2 C129.2 C130.2 C132.2 C133.2 C136.2 C143.2 C147.2 C153.2 C154.2 C155.2 C158.2 C164.2 C165.2 C281.2 C282.2 C283.2 C284.2 C524.2 C525.2 C534.2 C544.2 C545.2 C550.2 C551.2 C556.2 C557.2 C558.2 C563.2 C564.2 C570.2 C579.2 C580.2 C581.2 C582.2 C583.2 C590.2 C592.2 C596.2 C597.2 C598.2 D25.1(ANODE) J14.2 Q3.1(SOURCE) Q3.2(SOURCE) Q3.3(SOURCE) Q17.3(C) R29.1 R38.2 R44.1 R60.1 R78.2 R81.2 R87.2 R88.2 R89.1 R90.2 R95.2 R204.1 R233.1 T1.4 U7.13(GND) U9.10(PGND1) U9.22(SGND) U9.25(PGND2) U11.8(AGND) U11.10(PGND) U11.17(PAD) U12.8(AGND) U12.10(PGND) U12.17(PAD) U38.4(STBY) U38.5(ICTEST1) U38.14(SGND1) U38.15(SGND2) U38.32(SGND3) U38.47(ICTEST2) U38.48(SGND4) U38.57(EPGND) ; also on sheet 5 6 7 8 9 10 11 12 13 14 15 16 17 18 19 20 21
GND_SIGNAL: C2.2 C21.1 C170.2 C173.2 C174.2 C175.2 C178.1 C181.2 C183.2 C184.2 R2.1 R3.2 R4.2 R13.2 R186.1 R190.2 R191.2 R192.2 T1.3 T2.2 U1.13(SYNC) U1.19(SENSE-) U1.26(VNEG1) U1.27(VNEG2) U1.33(EP_GND)
12: D1.A D22.C ; also on sheet 14 17
34: D3.A D20.C ; also on sheet 14 17
56: D2.A D21.C ; also on sheet 14 17
78: D4.A D19.C ; also on sheet 14 17
AQR105_FLASH: C596.1 U38.28(LDO3) ; also on sheet 5 16 17
AQR105_VA12: C63.1 R83.2 U12.3(OUT1) U12.4(OUT2) ; also on sheet 9 11 16 17 21
AQR105_VA22: C62.1 R85.1 U11.3(OUT1) U11.4(OUT2) ; also on sheet 17
AQR105_VDD: C61.1 C68.1 C69.1 C70.1 L16.2 R82.1 U9.9(VON) ; also on sheet 17
D1_MVREF: C564.1 U38.31(REFOUT) ; also on sheet 5
DCDC2_3V3: C283.1 C284.1 C524.1 C525.1 C534.1 C544.1 C545.1 C550.1 C551.1 C556.1 C557.1 C558.1 C563.1 C570.1 C579.1 C580.1 C581.1 C582.1 C583.1 C592.1 C598.1 J19.3 R167.2 U11.12(IN1) U11.14(IN2) U12.9(~{SHDN}) U12.12(IN1) U12.14(IN2) U38.7(PVIN1_1) U38.10(PVIN1_2) U38.12(PVIN1_3) U38.17(VLDOIN1) U38.20(PVIN4) U38.23(PVIN2_1) U38.24(PVIN2_2) U38.27(VLDOIN23) U38.34(PVIN3_1) U38.37(PVIN3_2) U38.40(VLDOIN45) U38.50(VIN) U38.55(VCCI2C) ; also on sheet 6 7 8 10 11 13 14 15 18 19 20 21
DCDC2_3V3_PG: R167.1 U38.56(EN) ; also on sheet 20
DCDC_5V0: C10.1 C15.1 L11.2 U7.11(VOUT) ; also on sheet 10
DDR4_VDD: C133.1 C136.1 C143.1 C145.1 L21.2 U38.30(REFIN) U38.38(FB3) ; also on sheet 5 11
DDR4_VTT: C158.1 C164.1 C165.1 L23.2 U38.19(FB4) ; also on sheet 5
I2C1_SCL: J14.1 U38.54(SCL) ; also on sheet 8 13 18
I2C1_SDA: J14.3 U38.53(SDA) ; also on sheet 8 13 18
INTVCC: C71.1 D8.A R80.2 R92.1 R93.2 U9.3(MODE) U9.21(INTVCC)
POE_12V: L13.2 R61.1 ; also on sheet 21
VCORE_EN: C597.1 U38.26(LDO2) ; also on sheet 20
VR500_1V5: C116.1 C122.1 C130.1 C132.1 L22.1 U38.13(FB1) ; also on sheet 18
N24081686: L22.2 U38.8(LX1_1) U38.9(LX1_2) U38.11(LX1_3)
N24082962: L24.2 U38.22(LX2)
N24084401: L21.1 U38.35(LX3_1) U38.36(LX3_2)
N24085678: L23.1 U38.21(LX4)
N24088889: TP19.1(Pin1) U38.39(LDO4)
N24089783: C145.2 C147.1 U38.29(VHALF)
N24092126: C125.1 U38.51(VDIG)
N24092316: C126.1 U38.49(VCC)
N24092557: C124.1 U38.52(VBG)
N24092669: C129.1 U38.43(VBIAS)
N24105172: C1.1 C2.1 D1.C D2.C D3.C D4.C D23.C L9.1 R189.1 U1.32(VPORTP)
N24105186: C1.2 D19.A D20.A D21.A D22.A D23.A R185.1 U1.1(SHDN) U1.5(VPORTN1) U1.6(VPORTN2)
N24105908: R185.2 U1.3(RCLASS)
N24106035: C181.1 R189.2 R192.1 TP3.1(Pin1) U1.18(UVLO) U1.29(PWRGD)
N24106207: R1.1 R2.2 U1.16(FB)
N24106733: C170.1 C175.1 R187.2 R188.2 U1.10(VCC)
N24106981: C183.1 L9.2 R188.1 R195.1 T2.5
N24107203: R14.1 U1.24(PG)
N24107357: C177.2 C178.2 U1.17(VCMP)
N24107470: R196.1 U1.9(SG)
N24107483: C188.1 R196.2
N24107486: C188.2 T1.1
N24107616: C208.1 T1.6
N24107621: C208.2 D25.3(CATHODE) R204.2 R208.2
N24107777: Q3.4(GATE) Q17.2(E) Q18.2(EMITTER)
N24107780: Q17.1(B) Q18.1(BASE) R208.1
N24107840: C40.1 Q18.3(COLLECTOR) R47.2 R61.2
N24107947: D7.C R47.1
N24107950: D7.A Q3.5(DRAIN_1) Q3.6(DRAIN_2) Q3.7(DRAIN_3) Q3.8(DRAIN_4) R42.1 T2.6
N24108405: C27.1 R42.2
N24108768: C28.1 C38.1 L13.1 T2.10
N24108952: Q2.1(SOURCE) Q2.2(SOURCE) Q2.3(SOURCE) R13.1 U1.20(SENSE+)
N24109652: C184.1 U1.21(CCMP)
N24109671: R191.1 U1.22(RCMP)
N24109742: R3.1 U1.12(ENDLY)
N24109897: C173.1 U1.15(OSC)
N24109974: R190.1 U1.23(PGDLY)
N24109983: R4.1 U1.11(TON)
N24110294: C174.1 U1.14(SFST)
N24169528: R85.2 R87.1 U11.7(SENSE/ADJ)
N24414694: TP2.1(Pin1) U1.30(~{PWRGD})
N24414710: TP1.1(Pin1) U1.2(~{T2P})
N24480234: R33.1 R38.1 U7.6(MODE/SYNC)
N24480259: C19.2 R33.2 R45.2 R54.2 U7.4(PGFB) U7.10(INTVCC)
N24480273: C217.1 L11.1 U7.7(SW)
N24480332: C41.1 R60.2 U7.1(ISET)
N24480366: R29.2 R36.2 U7.5(RUN)
N24480391: C217.2 U7.9(BOOST)
N24480399: R44.2 R45.1 U7.3(RT)
N24480593: C43.2 R48.2 R54.1 U7.2(ITH)
N24480595: C32.2 R48.1
N24544266: TP50.1(Pin1) U38.3(~{POR})
N24584329: TP18.1(Pin1) U38.41(LDO5)
N24605281: TP57.1(Pin1) U38.1(~{INT})
N24932777: D24.1(ANODE1) R1.2 T2.1
N24935123: D24.3(CATHODE1) R187.1
N24935830: C186.2 Q2.5(DRAIN_1) Q2.6(DRAIN_2) Q2.7(DRAIN_3) Q2.8(DRAIN_4) T2.3
N24935853: C186.1 R195.2
N24936812: Q2.4(GATE) R14.2
N24970769: R83.1 R88.1 U12.7(SENSE/ADJ)
N24994453: R95.1 R96.2 U11.9(~{SHDN})
N25029315: C177.1 R186.2
N25157671: J21.2 R79.2
N25157693: C61.2 R81.1 R82.2 U9.4(FB)
N25157716: C75.2 D8.C U9.20(BOOST)
N25157741: C75.1 L16.1 U9.11(SW1) U9.12(SW2) U9.13(SW3) U9.14(SW4) U9.15(SW5) U9.16(SW6)
N25157783: C67.1 R91.2 U9.19(SVIN)
N25157815: R78.1 R79.1 U9.7(RUN)
N25157819: C281.1 U9.5(TRACK/SS)
N25157835: R233.2 U9.1(RT)
N25157944: R89.2 R90.1 R92.2 R93.1 U9.2(PHMODE)
N25158030: C53.1 R77.1 R80.1 U9.6(ITH)
N25158044: C52.1 R77.2
N26682338: J19.2 R96.1
N26683109: J20.2 R36.1

Not connected (* = marked no-connect by the designer): D24 2(NC)*; D25 2(NC)*; T1 2(NC1)* 5(NC2)*; T2 4(NC1)* 7(NC2)* 8(NC3)* 9(NC4)*; U1 4(NC1)* 7(NC2)* 8(NC3)* 25(NC4)* 28(NC5)* 31(NC6)*; U7 12(PGOOD)*; U9 8(PGOOD)* 23(CLKOUT)* 24(CLKIN)*; U11 1(NC1)* 2(NC2)* 5(NC3)* 6(NC4)* 11(NC5)* 13(NC6)* 15(NC7)* 16(NC8)*; U12 1(NC1)* 2(NC2)* 5(NC3)* 6(NC4)* 11(NC5)* 13(NC6)* 15(NC7)* 16(NC8)*; U38 2(DNC1)* 6(DNC2)* 16(DNC3)* 33(DNC4)* 42(DNC5)* 44(DNC6)* 45(DNC7)* 46(DNC8)*

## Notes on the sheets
sheet 22
- POE 12V/2.1A, 802.3.at
sheet 23
- USB POWER
- IND PWR 2.2UH@100KHZ
   0.03 OHM 2.95A 30% SMT
- AQR105 450mA
- 1A
- CER X5R
- TVDD at CPU power
  sequence 1
  AQR105 VA12 360mA
  500mA
- IND PWR 1UH@100KHZ
   5A 20% SMT
sheet 24
- 2.5A
- 1A
- 1A
- 1.5A
- When INT assert,
  CPU can read via I2C1
  what event happen
  Refet to datasheet
  table 81
- I2C1 ADDR:0X08
- 200mA
- DDR VPP and AQR105 IO
- 200mA
